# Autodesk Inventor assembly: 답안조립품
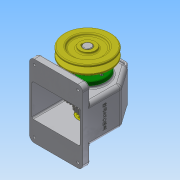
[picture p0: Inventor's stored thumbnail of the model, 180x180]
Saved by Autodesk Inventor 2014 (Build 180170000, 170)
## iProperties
Created: 2016-12
Part Number: 답안조립품
Document SubType Name: Assembly
Designer: user
Author: user
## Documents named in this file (15)
- C:\Users\user\Desktop\461208V1025\답안조립품.iam
- C:\Users\user\Desktop\461208V1025\본체.ipt
- C:\Users\user\Desktop\461208V1025\볼트 M3 x 8.ipt
- C:\Users\user\Desktop\461208V1025\볼트 M3 x 10.ipt
- C:\Users\user\Desktop\461208V1025\부시.ipt
- C:\Users\user\Desktop\461208V1025\스퍼기어.ipt
- C:\Users\user\Desktop\461208V1025\앞커버.ipt
- C:\Users\user\Desktop\461208V1025\오일씰 28 40 8.ipt
- C:\Users\user\Desktop\461208V1025\축.ipt
- C:\Users\user\Desktop\461208V1025\키 - 5 x 5 x 18.ipt
- C:\Users\user\Desktop\461208V1025\키 - 6 x 6 x 22.ipt
- C:\Users\user\Desktop\461208V1025\V-벨트풀리.ipt
- C:\Users\user\Desktop\461208V1025\뒤커버.ipt
- C:\Users\user\Desktop\461208V1025\멈춤나사 - M4x10.ipt
- C:\Users\user\Desktop\461208V1025\베어링 6203.ipt
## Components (9 placed, 3 different names)
1. V-벨트풀리:1 — Insert:14, Angle:4
2. ISO 4762 M3 x 8:1 — Insert:13
3. ISO 4762 M3 x 8:2
4. ISO 4762 M3 x 8:3
5. ISO 4762 M3 x 8:4
6. ISO 4762 M3 x 10:1 — Insert:12
7. ISO 4762 M3 x 10:2
8. ISO 4762 M3 x 10:3
9. ISO 4762 M3 x 10:4
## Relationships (4: Insert 3, Angle 1)
- Insert:12: ISO 4762 M3 x 10:1
- Insert:13: ISO 4762 M3 x 8:1
- Insert:14: V-벨트풀리:1
- Angle:4: V-벨트풀리:1
